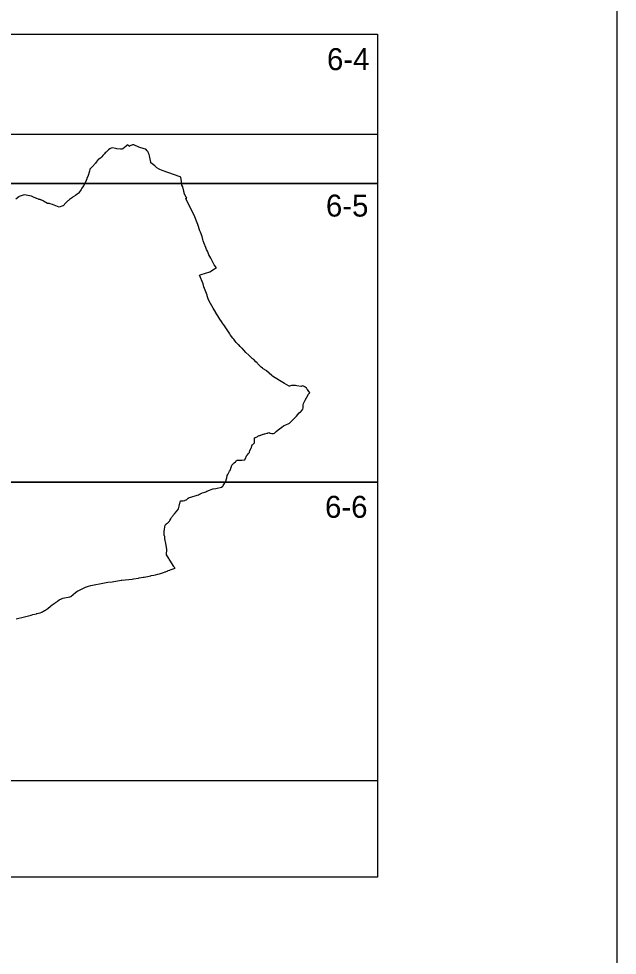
# Model space of a CAD drawing. Extents: x -447552 to -439754, y -1129367 to -1125104.
# Drawn here: x -443174.5 to -442923.9, y -1128963.9 to -1128571.9 of the extents above; entities that cross this region are included whole.
import ezdxf

# ---------------------------------------------------------------- set-up
doc = ezdxf.new("R2010")
doc.units = 0
for name, color, linetype in [('Vrstva 1', 7, 'Continuous'), ('Vrstva 10', 7, 'Continuous'), ('Vrstva 4', 7, 'Continuous'), ('Vrstva 63', 7, 'Continuous')]:
    doc.layers.add(name, color=color, linetype=linetype)

msp = doc.modelspace()

# ---------------------------------------------------------------- linework, layer by layer
at = {"layer": 'Vrstva 1'}
msp.add_lwpolyline([(-443175.6, -1128823.09), (-443172.06, -1128822.22), (-443169.29, -1128821.55), (-443168.62, -1128821.34), (-443167.13, -1128820.98), (-443166.92, -1128820.92), (-443165.49, -1128820.53), (-443164.89, -1128820.27), (-443164.67, -1128820.17), (-443164.51, -1128820.11), (-443163.69, -1128819.66), (-443163.63, -1128819.62), (-443162.32, -1128818.84), (-443161.17, -1128817.79), (-443160.52, -1128817.29), (-443160.39, -1128817.18), (-443160.37, -1128817.17), (-443160.21, -1128817.04), (-443160.06, -1128816.94), (-443159.26, -1128816.38), (-443159.2, -1128816.34), (-443159.13, -1128816.29), (-443158.62, -1128815.94), (-443158.25, -1128815.68), (-443157.59, -1128815.22), (-443157, -1128814.81), (-443156.84, -1128814.84), (-443156.83, -1128814.84), (-443156.81, -1128814.82), (-443156.08, -1128814.43), (-443153.12, -1128813.85), (-443152.7, -1128813.7), (-443150.67, -1128812.07), (-443150.2, -1128811.73), (-443150.17, -1128811.71), (-443149.81, -1128811.45), (-443149.63, -1128811.33), (-443148.24, -1128810.63), (-443146.83, -1128809.99), (-443146.53, -1128809.84), (-443145.27, -1128809.38), (-443144.27, -1128809.13), (-443138.56, -1128808.07), (-443137.14, -1128807.81), (-443135.43, -1128807.56), (-443131.56, -1128806.99), (-443131.32, -1128806.96), (-443127.02, -1128806.44), (-443126.49, -1128806.38), (-443124.34, -1128806.02), (-443124.02, -1128805.97), (-443122.36, -1128805.7), (-443121.96, -1128805.63), (-443120.55, -1128805.34), (-443119.26, -1128805.07), (-443119.05, -1128805.03), (-443117.88, -1128804.8), (-443117.21, -1128804.67), (-443117.19, -1128804.67), (-443116.28, -1128804.46), (-443116.21, -1128804.44), (-443115.56, -1128804.28), (-443115.21, -1128804.17), (-443114.32, -1128803.88), (-443113.88, -1128803.73), (-443113.23, -1128803.49), (-443113.11, -1128803.45), (-443112.02, -1128802.96), (-443112.02, -1128802.96), (-443111.9, -1128802.92), (-443111.25, -1128802.69), (-443111.16, -1128802.66), (-443110.73, -1128802.5), (-443109.07, -1128801.92), (-443109.09, -1128801.87), (-443109.2, -1128801.7), (-443109.36, -1128801.47), (-443109.58, -1128801.15), (-443111.28, -1128798.51), (-443111.49, -1128798.16), (-443111.66, -1128797.89), (-443112.1, -1128797.18), (-443112.63, -1128796.33), (-443112.47, -1128793.97), (-443112.46, -1128793.88), (-443112.85, -1128791.58), (-443112.85, -1128791.56), (-443112.86, -1128791.54), (-443112.86, -1128791.54), (-443112.86, -1128791.51), (-443113.27, -1128789.68), (-443113.28, -1128789.49), (-443113.34, -1128788.69), (-443113.44, -1128788.41), (-443113.45, -1128788.39), (-443113.56, -1128788.17), (-443113.6, -1128788.09), (-443113.61, -1128787.71), (-443113.64, -1128787.01), (-443113.59, -1128786.52), (-443113.59, -1128786.5), (-443113.5, -1128785.64), (-443113.48, -1128785.53), (-443113.19, -1128783.89), (-443113.11, -1128783.81), (-443112.81, -1128783.47), (-443112.75, -1128783.4), (-443112.49, -1128783.28), (-443112.43, -1128783.22), (-443112.17, -1128783.02), (-443111.94, -1128782.84), (-443111.73, -1128782.68), (-443111.67, -1128782.64), (-443111.59, -1128782.51), (-443111.51, -1128782.39), (-443111.4, -1128782.22), (-443111.18, -1128781.89), (-443110.76, -1128781.24), (-443110.63, -1128780.99), (-443110.62, -1128780.98), (-443110.48, -1128780.69), (-443110.43, -1128780.6), (-443110.25, -1128780.27), (-443110.11, -1128780.12), (-443109.81, -1128779.81), (-443109.64, -1128779.63), (-443109.36, -1128779.28), (-443109.23, -1128779.11), (-443108.54, -1128778.26), (-443107.88, -1128777.45), (-443107.59, -1128777.09), (-443107.35, -1128775.92), (-443107.29, -1128775.69), (-443107.22, -1128775.41), (-443106.9, -1128774.1), (-443106.82, -1128773.82), (-443106.82, -1128773.79), (-443106.8, -1128773.74), (-443106.64, -1128773.73), (-443106.62, -1128773.73), (-443106.38, -1128773.73), (-443105.69, -1128773.71), (-443105.68, -1128773.71), (-443105.65, -1128773.71), (-443104.97, -1128773.53), (-443104.77, -1128773.47), (-443104.35, -1128773.36), (-443104.33, -1128773.35), (-443104.27, -1128773.29), (-443103.97, -1128773.01), (-443103.85, -1128772.93), (-443103.51, -1128772.67), (-443103.09, -1128772.35), (-443103.02, -1128772.33), (-443102.46, -1128772.17), (-443099.76, -1128771.41), (-443099.17, -1128771.14), (-443098.84, -1128770.98), (-443098.79, -1128770.96), (-443098.69, -1128770.91), (-443098.33, -1128770.73), (-443098.28, -1128770.71), (-443098.25, -1128770.69), (-443098.24, -1128770.69), (-443098.21, -1128770.67), (-443097.9, -1128770.52), (-443097.84, -1128770.48), (-443097.73, -1128770.43), (-443096.65, -1128770.1), (-443096.22, -1128769.92), (-443095.7, -1128769.7), (-443094.69, -1128769.29), (-443093.27, -1128768.66), (-443093.13, -1128768.65), (-443092, -1128768.6), (-443089.6, -1128768.04), (-443089.07, -1128767.64), (-443089, -1128767.52), (-443088.91, -1128767.34), (-443088.65, -1128766.83), (-443088.3, -1128766.4), (-443088.28, -1128766.37), (-443088.07, -1128766.08), (-443087.96, -1128765.92), (-443087.95, -1128765.91), (-443087.41, -1128764.13), (-443087.4, -1128764.1), (-443087.2, -1128763.15), (-443086.94, -1128762.69), (-443086.75, -1128762.36), (-443086.2, -1128761.24), (-443085.82, -1128760.73), (-443085.79, -1128760.6), (-443085.72, -1128760.3), (-443085.69, -1128760.16), (-443085.63, -1128759.91), (-443085.61, -1128759.81), (-443085.29, -1128758.8), (-443085.28, -1128758.79), (-443084.99, -1128758.51), (-443084.33, -1128757.88), (-443084.28, -1128757.83), (-443083.81, -1128757.35), (-443083.55, -1128757.09), (-443083.45, -1128756.98), (-443083.08, -1128756.66), (-443083.04, -1128756.66), (-443083.03, -1128756.66), (-443082.62, -1128756.65), (-443082.45, -1128756.66), (-443081.82, -1128756.68), (-443081.11, -1128756.68), (-443080.14, -1128756.59), (-443080.11, -1128756.59), (-443079.86, -1128756.56), (-443079.64, -1128756.2), (-443079.59, -1128756.07), (-443079.57, -1128756.02), (-443079.55, -1128755.96), (-443079.19, -1128754.94), (-443079.05, -1128754.77), (-443078.95, -1128754.66), (-443078.91, -1128754.62), (-443078.85, -1128754.54), (-443078.73, -1128754.41), (-443078.46, -1128754.09), (-443078.37, -1128753.99), (-443078.27, -1128753.87), (-443077.93, -1128753.48), (-443077.86, -1128753.09), (-443077.8, -1128752.78), (-443077.73, -1128752.65), (-443077.18, -1128751.73), (-443077.07, -1128751.34), (-443076.88, -1128750.64), (-443076.76, -1128750.35), (-443076.47, -1128750.08), (-443075.92, -1128749.57), (-443075.85, -1128749.51), (-443075.75, -1128747.4), (-443074.73, -1128746.91), (-443074.33, -1128746.7), (-443074.08, -1128746.57), (-443073.79, -1128746.41), (-443073.57, -1128746.33), (-443073.23, -1128746.2), (-443073.18, -1128746.19), (-443072.09, -1128745.78), (-443072.08, -1128745.78), (-443071.59, -1128745.72), (-443071.51, -1128745.7), (-443070.48, -1128745.44), (-443070.33, -1128745.4), (-443070.24, -1128745.37), (-443070.07, -1128745.32), (-443069.54, -1128745.15), (-443069.54, -1128745.15), (-443069.53, -1128745.16), (-443069.53, -1128745.16), (-443069.5, -1128745.22), (-443069.37, -1128745.44), (-443068.49, -1128745.54), (-443068.29, -1128745.56), (-443067.93, -1128745.6), (-443067.84, -1128745.56), (-443067.41, -1128745.38), (-443066.76, -1128744.67), (-443065.12, -1128743.51), (-443065.03, -1128743.44), (-443064.86, -1128743.33), (-443064.35, -1128742.91), (-443063.6, -1128742.31), (-443062.33, -1128741.74), (-443061.71, -1128741.47), (-443061.17, -1128741.23), (-443061.11, -1128741.2), (-443059.46, -1128739.53), (-443058.62, -1128738.64), (-443058.26, -1128738.26), (-443057.07, -1128736.9), (-443056.47, -1128736.44), (-443056.42, -1128736.4), (-443055.58, -1128735.39), (-443055.38, -1128734.82), (-443055.47, -1128733.49), (-443055.25, -1128733), (-443054.61, -1128731.55), (-443053.15, -1128729.07), (-443053.12, -1128729.02), (-443053.12, -1128729.02), (-443053.1, -1128728.99), (-443053.07, -1128728.95), (-443052.92, -1128728.76), (-443052.66, -1128728.42), (-443052.92, -1128728.12), (-443053.06, -1128727.9), (-443053.53, -1128727.16), (-443053.73, -1128726.97), (-443053.88, -1128726.81), (-443054.07, -1128726.61), (-443054.65, -1128726.04), (-443055.5, -1128725.57), (-443055.95, -1128725.75), (-443056.28, -1128725.87), (-443058.03, -1128725.6), (-443058.64, -1128725.51), (-443058.78, -1128725.5), (-443059.37, -1128725.48), (-443059.75, -1128725.43), (-443059.91, -1128725.4), (-443059.95, -1128725.4), (-443059.98, -1128725.39), (-443059.98, -1128725.39), (-443060.01, -1128725.4), (-443060.11, -1128725.43), (-443060.24, -1128725.46), (-443061.14, -1128725.7), (-443061.21, -1128725.67), (-443063.28, -1128724.63), (-443065.3, -1128723.35), (-443068.21, -1128721.53), (-443068.37, -1128721.39), (-443068.41, -1128721.36), (-443068.5, -1128721.28), (-443069.64, -1128720.35), (-443070.79, -1128719.3), (-443070.9, -1128719.2), (-443072.11, -1128718.44), (-443072.39, -1128718.21), (-443073.02, -1128717.71), (-443073.33, -1128717.47), (-443073.83, -1128716.94), (-443074.55, -1128716.18), (-443074.7, -1128716.02), (-443075.16, -1128715.53), (-443076.13, -1128714.5), (-443076.33, -1128714.39), (-443076.33, -1128714.39), (-443076.51, -1128714.3), (-443076.71, -1128714.2), (-443077.54, -1128713.37), (-443078.17, -1128712.74), (-443079.35, -1128711.57), (-443080.28, -1128710.63), (-443080.44, -1128710.48), (-443080.88, -1128710.03), (-443081.12, -1128709.79), (-443081.21, -1128709.7), (-443081.25, -1128709.66), (-443081.77, -1128709.14), (-443082.41, -1128708.49), (-443082.49, -1128708.41), (-443082.51, -1128708.39), (-443082.66, -1128708.24), (-443083.49, -1128707.4), (-443083.87, -1128706.9), (-443084.15, -1128706.53), (-443084.47, -1128706.1), (-443084.83, -1128705.62), (-443085.78, -1128704.36), (-443086.15, -1128703.82), (-443088.69, -1128700.08), (-443088.86, -1128699.82), (-443089.63, -1128698.63), (-443090.3, -1128697.62), (-443091.14, -1128696.29), (-443091.94, -1128695.02), (-443092.02, -1128694.89), (-443093.11, -1128693.04), (-443094.79, -1128690.19), (-443094.79, -1128690.18), (-443094.79, -1128690.18), (-443094.8, -1128690.18), (-443095.13, -1128689.2), (-443095.58, -1128687.9), (-443095.64, -1128687.7), (-443097.02, -1128684.19), (-443097.31, -1128682.94), (-443098.79, -1128679.26), (-443098.16, -1128679.06), (-443094.44, -1128677.82), (-443092.47, -1128676.6), (-443092.29, -1128676.49), (-443092.23, -1128676.45), (-443092.03, -1128676.33), (-443091.76, -1128676.16), (-443092.68, -1128674.97), (-443094.09, -1128672.19), (-443094.84, -1128670.72), (-443095.37, -1128669.56), (-443095.39, -1128669.52), (-443095.45, -1128669.39), (-443095.46, -1128669.36), (-443095.48, -1128669.33), (-443095.52, -1128669.24), (-443095.85, -1128668.51), (-443096.17, -1128667.72), (-443096.88, -1128665.95), (-443097.29, -1128664.91), (-443097.44, -1128664.28), (-443097.7, -1128663.15), (-443098.44, -1128661.26), (-443098.64, -1128660.66), (-443099.58, -1128658.03), (-443099.85, -1128657.31), (-443101.04, -1128654.22), (-443101.11, -1128654.04), (-443101.14, -1128653.96), (-443104.49, -1128647.15), (-443104.18, -1128647.01), (-443104.16, -1128647), (-443104.26, -1128646.83), (-443104.34, -1128646.73), (-443104.51, -1128646.5), (-443104.57, -1128646.42), (-443105.18, -1128644.94), (-443105.23, -1128644.65), (-443105.33, -1128644.19), (-443105.34, -1128644.13), (-443105.85, -1128642.29), (-443106.15, -1128641.66), (-443106.16, -1128641.58), (-443106.2, -1128641.22), (-443106.34, -1128640.13), (-443106.62, -1128638.29), (-443106.68, -1128638.27), (-443106.98, -1128638.17), (-443107.36, -1128637.91), (-443107.37, -1128637.91), (-443111.67, -1128636.5), (-443114.46, -1128635.52), (-443115.77, -1128634.9), (-443116.74, -1128634.34), (-443117.46, -1128633.56), (-443119.14, -1128632.29), (-443119.2, -1128631.99), (-443119.78, -1128629.29), (-443119.93, -1128628.75), (-443120.11, -1128628.24), (-443120.16, -1128628.08), (-443120.41, -1128627.56), (-443120.66, -1128627.25), (-443121.24, -1128626.56), (-443121.99, -1128626.35), (-443124.17, -1128625.69), (-443126.26, -1128624.73), (-443126.88, -1128624.73), (-443127.83, -1128625.1), (-443127.96, -1128625.19), (-443128.03, -1128625.24), (-443128.17, -1128625.34), (-443128.21, -1128625.37), (-443128.23, -1128625.35), (-443128.44, -1128625.1), (-443128.69, -1128624.82), (-443128.77, -1128624.72), (-443128.86, -1128624.76), (-443129.37, -1128625.15), (-443129.56, -1128625.3), (-443130.23, -1128625.82), (-443130.98, -1128626.38), (-443131.32, -1128626.6), (-443131.91, -1128626.56), (-443133.39, -1128626.41), (-443133.85, -1128626.32), (-443135.44, -1128626), (-443135.74, -1128626.11), (-443136.3, -1128626.46), (-443136.85, -1128626.78), (-443137.34, -1128627.24), (-443137.87, -1128627.73), (-443138.27, -1128628.12), (-443138.28, -1128628.13), (-443138.61, -1128628.47), (-443138.74, -1128628.61), (-443139.25, -1128629.16), (-443139.7, -1128629.71), (-443139.86, -1128629.9), (-443140.22, -1128630.33), (-443140.96, -1128630.66), (-443140.98, -1128630.66), (-443141.18, -1128630.91), (-443142.04, -1128631.93), (-443142.42, -1128632.38), (-443143.55, -1128633.74), (-443143.56, -1128633.75), (-443144.8, -1128634.92), (-443144.92, -1128635.76), (-443144.97, -1128636.13), (-443145.01, -1128636.23), (-443145.49, -1128637.58), (-443145.93, -1128638.82), (-443145.96, -1128638.9), (-443146.26, -1128639.59), (-443147.19, -1128641.77), (-443147.21, -1128641.78), (-443147.78, -1128642.46), (-443148.08, -1128642.81), (-443148.08, -1128642.82), (-443148.42, -1128643.36), (-443149.29, -1128644.75), (-443149.38, -1128644.89), (-443149.55, -1128645.02), (-443150.08, -1128645.41), (-443150.69, -1128645.86), (-443150.69, -1128645.86), (-443151.66, -1128646.49), (-443151.79, -1128646.58), (-443151.97, -1128646.7), (-443153.27, -1128647.56), (-443153.28, -1128647.57), (-443153.54, -1128647.83), (-443153.66, -1128647.95), (-443153.88, -1128648.18), (-443154.16, -1128648.46), (-443154.73, -1128649.03), (-443155.89, -1128650.19), (-443156.09, -1128650.27), (-443157.59, -1128650.84), (-443160.4, -1128649.72), (-443160.4, -1128649.73), (-443160.41, -1128649.75), (-443161.32, -1128649.37), (-443161.63, -1128649.24), (-443161.65, -1128649.24), (-443162.04, -1128649.24), (-443162.52, -1128649.24), (-443164.08, -1128648.25), (-443164.34, -1128648.12), (-443164.63, -1128647.96), (-443164.69, -1128647.93), (-443164.73, -1128647.91), (-443165.27, -1128647.68), (-443165.32, -1128647.68), (-443165.33, -1128647.68), (-443165.48, -1128647.67), (-443165.6, -1128647.66), (-443165.91, -1128647.64), (-443165.93, -1128647.64), (-443165.93, -1128647.64), (-443166.04, -1128647.6), (-443166.28, -1128647.5), (-443166.88, -1128647.25), (-443167.04, -1128647.18), (-443168.56, -1128646.45), (-443169.18, -1128646.27), (-443169.85, -1128646.07), (-443172.17, -1128645.64), (-443172.18, -1128645.64), (-443172.58, -1128645.75), (-443174.32, -1128646.33), (-443174.45, -1128646.44), (-443175.66, -1128647.4)], dxfattribs=at)
at = {"layer": 'Vrstva 10'}
msp.add_lwpolyline([(-443024.3, -1128620.23), (-443024.3, -1128931.21), (-443357.17, -1128931.21), (-443357.17, -1128765.91), (-443336.8, -1128765.91), (-443336.8, -1128640.91), (-443336.8, -1128620.23), (-443024.3, -1128620.23)], dxfattribs=at)
at = {"layer": 'Vrstva 4'}
msp.add_line((-443336.8, -1128578.41), (-443024.3, -1128578.41), dxfattribs=at)
msp.add_lwpolyline([(-443024.3, -1128578.41), (-443024.3, -1128640.91), (-443180.55, -1128640.91), (-443180.55, -1128578.41)], dxfattribs=at)
for points in [[(-443024.3, -1128640.91), (-443024.3, -1128765.91), (-443180.55, -1128765.91), (-443180.55, -1128640.91)], [(-443024.3, -1128765.91), (-443024.3, -1128890.91), (-443180.55, -1128890.91), (-443180.55, -1128765.91)]]:
    msp.add_lwpolyline(points, close=True, dxfattribs=at)
at = {"layer": 'Vrstva 63'}
msp.add_lwpolyline([(-444408.89, -1128316.81), (-444408.89, -1129366.81), (-442923.89, -1129366.81), (-442923.89, -1128316.81)], close=True, dxfattribs=at)

# ---------------------------------------------------------------- texts
at = {"layer": 'Vrstva 1'}
for s, p in [('6-4', (-443045.43, -1128593.46)), ('6-5', (-443045.88, -1128654.75)), ('6-6', (-443046.25, -1128780.82))]:
    msp.add_text(s, height=9.2, dxfattribs=at).set_placement(p)

doc.saveas('drawing.dxf')
